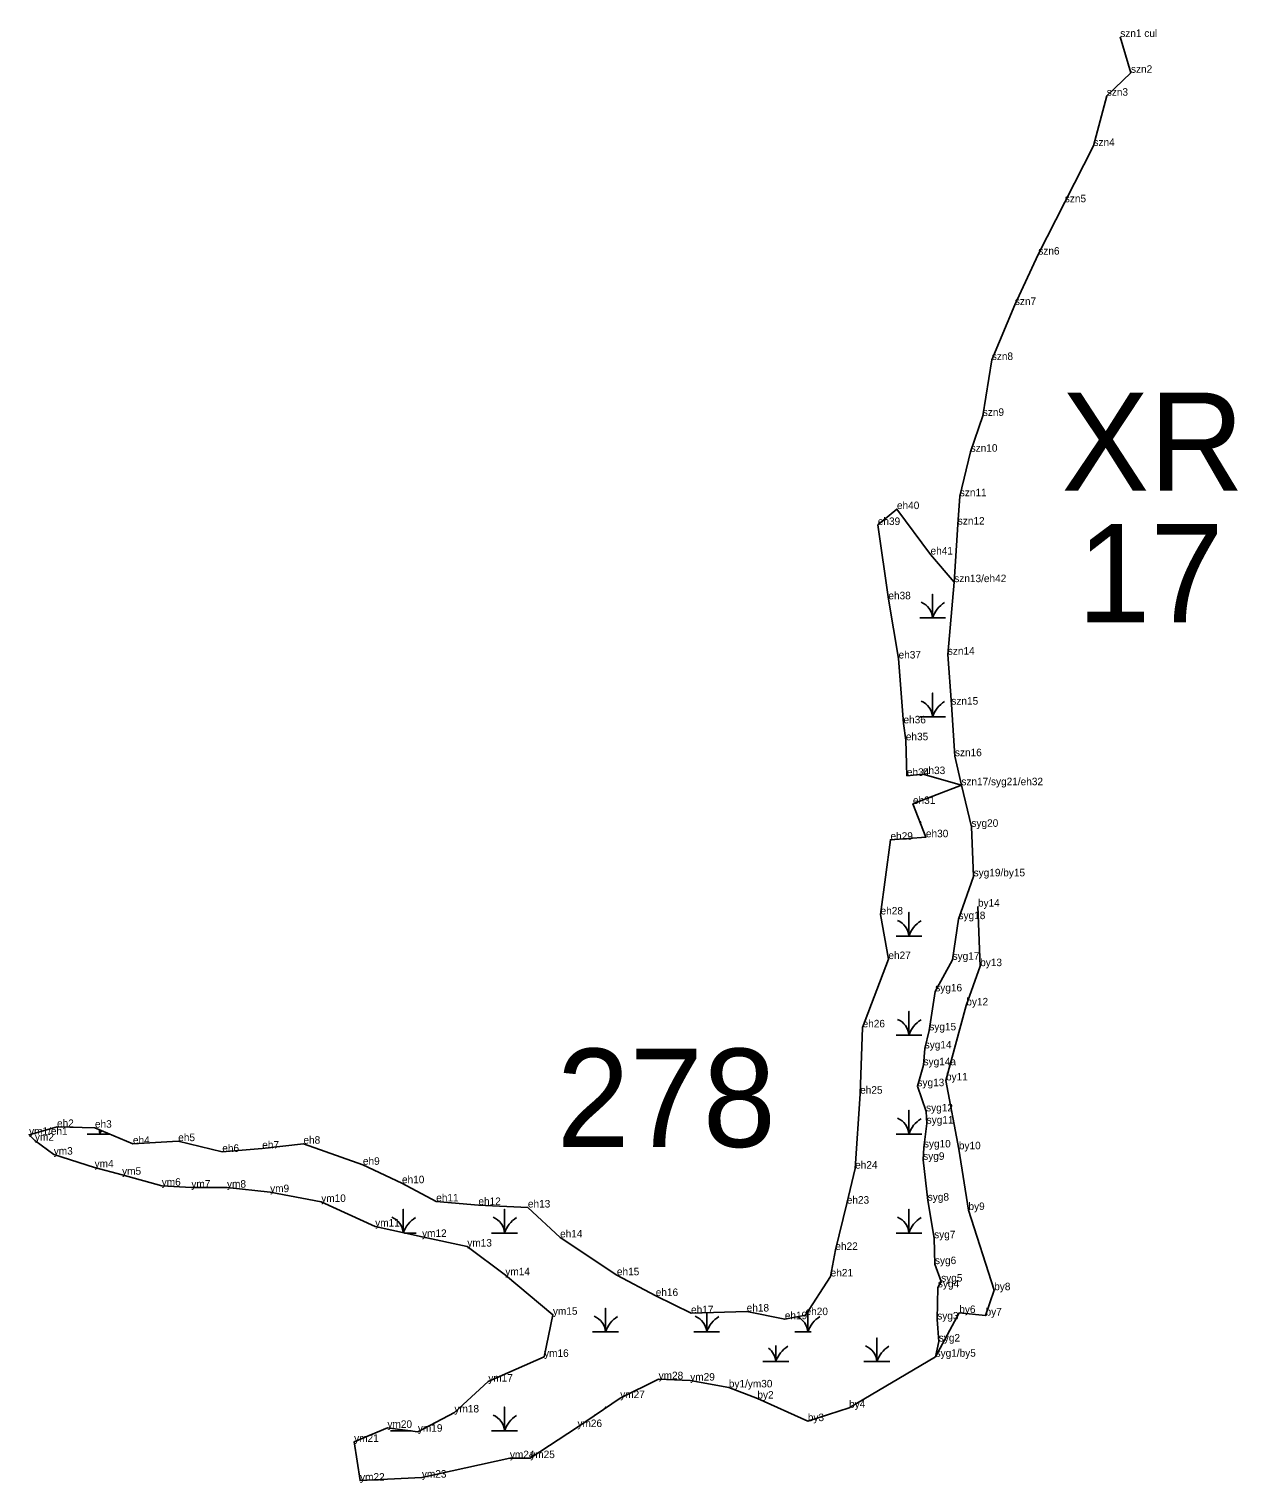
# Model space of a CAD drawing. Extents: x 2072529 to 2268796, y 436423 to 470406.
# Drawn here: x 2238515 to 2239319, y 438660 to 439627 of the extents above; entities that cross this region are included whole.
import ezdxf

# ---------------------------------------------------------------- set-up
doc = ezdxf.new("R2010")
doc.units = 0
for name, color, linetype in [('Default', 7, 'Continuous'), ('Exist Environmental Wetland Boundary', 7, 'Continuous'), ('Exist Environmental Wetland Boundary Cogo Comment', 7, 'Continuous'), ('Exist Hydro Jurisdictional Stream or Body of Water NEU Mitigable', 7, 'Continuous'), ('Exist Hydro Jurisdictional Stream or Body of Water NEU Mitigable Cogo Comment', 7, 'Continuous'), ('Exist Hydro Swamp or Marsh', 7, 'Continuous'), ('Old_Level_20', 7, 'Continuous')]:
    doc.layers.add(name, color=color, linetype=linetype)

msp = doc.modelspace()

# ---------------------------------------------------------------- linework, layer by layer
at = {"layer": 'Exist Environmental Wetland Boundary'}
for points in [[(2238980.17, 438723.98), (2238954.5, 438728.5), (2238933.48, 438729.42), (2238907.94, 438716.85), (2238879.5, 438697.62), (2238848.11, 438676.97), (2238834.56, 438676.88), (2238776.04, 438663.97), (2238734.94, 438661.98), (2238730.98, 438687.75), (2238753.14, 438697.08), (2238773.37, 438694.51), (2238797.69, 438707.34), (2238820.21, 438727.82), (2238857.31, 438744.3), (2238863.18, 438772.3), (2238831.54, 438798.55), (2238806.25, 438817.65), (2238776.16, 438824.05), (2238744.98, 438830.99), (2238709.11, 438847.32), (2238675.12, 438853.84), (2238646.44, 438856.82), (2238622.74, 438856.85), (2238603.03, 438858.12), (2238576.68, 438865.43), (2238558.41, 438870.32), (2238531.22, 438878.77), (2238518.73, 438888.08), (2238514.82, 438892), (2238533.4, 438897.17), (2238558.63, 438896.68), (2238583.89, 438885.99), (2238614, 438887.75), (2238643.32, 438880.62), (2238669.87, 438882.82), (2238697.27, 438886.05), (2238736.84, 438872.03), (2238762.81, 438859.76), (2238785.58, 438847.67), (2238813.64, 438845.28), (2238846.55, 438843.62), (2238867.95, 438823.73), (2238905.74, 438798.56), (2238931.56, 438784.78), (2238955.04, 438773.27), (2238992.04, 438774.46), (2239017.4, 438769.35), (2239031.2, 438772.05), (2239047.88, 438797.76), (2239051.03, 438815.39), (2239058.6, 438846.18), (2239064.17, 438869.46), (2239067.52, 438919.3), (2239069.12, 438963.43), (2239086.29, 439008.83), (2239081.09, 439038.49), (2239087.68, 439088.18), (2239111.25, 439089.84), (2239102.62, 439111.99), (2239134.83, 439124.43), (2239109.21, 439131.85), (2239098.58, 439130.7), (2239097.89, 439154.34), (2239096.33, 439165.59), (2239093.07, 439208.73), (2239086.28, 439248.1), (2239079.24, 439297.52), (2239091.98, 439308.07), (2239114.33, 439277.88), (2239130.1, 439259.51)], [(2238980.17, 438723.98), (2238999.17, 438716.6), (2239032.71, 438701.56), (2239060.14, 438710.42), (2239117.66, 438744.38), (2239133.42, 438773.47), (2239150.91, 438771.79), (2239156.64, 438788.62), (2239139.54, 438841.96), (2239133.15, 438882.35), (2239124.57, 438928.14), (2239138.11, 438978.03), (2239147.33, 439004.13), (2239145.84, 439043.72)]]:
    msp.add_lwpolyline(points, dxfattribs=at)
at = {"layer": 'Exist Hydro Jurisdictional Stream or Body of Water NEU Mitigable'}
msp.add_lwpolyline([(2239240.49, 439622.04), (2239247.61, 439598.24), (2239231.5, 439582.99), (2239222.67, 439549.6), (2239203.62, 439512.14), (2239185.96, 439477.33), (2239170.4, 439443.86), (2239155.04, 439407.24), (2239149.05, 439370.08), (2239140.98, 439346.22), (2239133.77, 439316.64), (2239132.43, 439297.8), (2239130.1, 439259.51), (2239125.8, 439211.29), (2239128.17, 439178.04), (2239130.54, 439143.75), (2239134.83, 439124.43), (2239141.51, 439096.78), (2239142.97, 439063.86), (2239132.92, 439035.39), (2239128.96, 439008.36), (2239117.45, 438987.35), (2239113.49, 438961.42), (2239110.45, 438949.43), (2239109.66, 438938.21), (2239105.6, 438924.29), (2239111.36, 438907.55), (2239111.76, 438899.44), (2239109.91, 438883.57), (2239109.43, 438875.34), (2239112.46, 438848.19), (2239116.71, 438823.21), (2239117.25, 438805.98), (2239121.39, 438794.34), (2239119.2, 438790.51), (2239118.77, 438769.16), (2239119.82, 438754.51), (2239117.66, 438744.38)], dxfattribs=at)
at = {"layer": 'Exist Hydro Swamp or Marsh'}
for points in [[(2239107.08, 439235.7), (2239115.68, 439235.7), (2239115.68, 439251.48), (2239115.68, 439235.7), (2239124.28, 439235.7)], [(2239107.08, 439169.9), (2239115.68, 439169.9), (2239115.68, 439185.68), (2239115.68, 439169.9), (2239124.28, 439169.9)], [(2239091.35, 439024.07), (2239099.95, 439024.07), (2239099.95, 439039.85), (2239099.95, 439024.07), (2239108.56, 439024.07)], [(2239091.35, 438958.27), (2239099.95, 438958.27), (2239099.95, 438974.05), (2239099.95, 438958.27), (2239108.56, 438958.27)], [(2239091.35, 438892.47), (2239099.95, 438892.47), (2239099.95, 438908.25), (2239099.95, 438892.47), (2239108.56, 438892.47)], [(2238553.35, 438892.47), (2238561.95, 438892.47), (2238561.95, 438895.27)], [(2238561.95, 438895.27), (2238561.95, 438892.47), (2238568.56, 438892.47)], [(2238763.7, 438826.83), (2238763.7, 438842.45), (2238763.7, 438826.83)], [(2238822.35, 438826.67), (2238830.95, 438826.67), (2238830.95, 438842.45), (2238830.95, 438826.67), (2238839.56, 438826.67)], [(2239091.35, 438826.67), (2239099.95, 438826.67), (2239099.95, 438842.45), (2239099.95, 438826.67), (2239108.56, 438826.67)], [(2238764.39, 438826.67), (2238772.31, 438826.67)], [(2238889.6, 438760.87), (2238898.2, 438760.87), (2238898.2, 438776.65), (2238898.2, 438760.87), (2238906.81, 438760.87)], [(2238956.85, 438760.87), (2238965.45, 438760.87), (2238965.45, 438773.6)], [(2238965.45, 438773.6), (2238965.45, 438760.87), (2238974.06, 438760.87)], [(2239024.1, 438760.87), (2239032.7, 438760.87), (2239032.7, 438774.37)], [(2239032.7, 438774.37), (2239032.7, 438760.87), (2239034.97, 438760.87)], [(2239002.78, 438741.14), (2239011.38, 438741.14), (2239011.38, 438751.82)], [(2239011.38, 438751.82), (2239011.38, 438741.14), (2239019.98, 438741.14)], [(2239070.03, 438741.14), (2239078.63, 438741.14), (2239078.63, 438756.92), (2239078.63, 438741.14), (2239087.23, 438741.14)], [(2238822.35, 438695.07), (2238830.95, 438695.07), (2238830.95, 438710.85), (2238830.95, 438695.07), (2238839.56, 438695.07)], [(2238898.2, 438710.26), (2238898.2, 438710.85), (2238898.2, 438710.26)], [(2238755.1, 438695.07), (2238763.7, 438695.07), (2238763.7, 438695.73)], [(2238763.7, 438695.73), (2238763.7, 438695.07), (2238768.92, 438695.07)]]:
    msp.add_lwpolyline(points, dxfattribs=at)
for centre, radius, start, end in [((2239103.42, 439234.81), 12.3, 4.14034, 67.53497), ((2239133.92, 439229.64), 19.22, 122.12745, 161.62219), ((2239103.42, 439169.01), 12.3, 4.14034, 67.53497), ((2239133.92, 439163.84), 19.22, 122.12745, 161.62219), ((2239118.2, 439083.81), 19.22, 122.12745, 124.16631), ((2239087.69, 439023.18), 12.3, 4.14034, 67.53497), ((2239118.2, 439018.01), 19.22, 122.12745, 161.62219), ((2239087.69, 438957.38), 12.3, 4.14034, 67.53497), ((2239118.2, 438952.21), 19.22, 122.12745, 161.62219), ((2239087.69, 438891.58), 12.3, 4.14034, 67.53497), ((2239118.2, 438886.41), 19.22, 122.12745, 161.62219), ((2238549.69, 438891.58), 12.3, 4.14034, 18.72156), ((2238580.2, 438886.41), 19.22, 153.93646, 161.62219), ((2238751.44, 438825.78), 12.3, 4.87114, 67.53497), ((2238781.95, 438820.61), 19.22, 122.12745, 161.17266), ((2238818.69, 438825.78), 12.3, 4.14034, 67.53497), ((2238849.2, 438820.61), 19.22, 122.12745, 161.62219), ((2239087.69, 438825.78), 12.3, 4.14034, 67.53497), ((2239118.2, 438820.61), 19.22, 122.12745, 161.62219), ((2238885.94, 438759.98), 12.3, 4.14034, 67.53497), ((2238916.45, 438754.81), 19.22, 122.12745, 161.62219), ((2238953.19, 438759.98), 12.3, 4.14034, 67.53497), ((2238983.7, 438754.81), 19.22, 122.12745, 161.62219), ((2239020.44, 438759.98), 12.3, 4.14034, 63.70318), ((2239050.95, 438754.81), 19.22, 122.12745, 161.62219), ((2239029.62, 438735.08), 19.22, 122.12745, 161.62219), ((2239066.36, 438740.25), 12.3, 4.14034, 67.53497), ((2239096.87, 438735.08), 19.22, 122.12745, 161.62219), ((2238999.11, 438740.25), 12.3, 4.14034, 52.40661), ((2238818.69, 438694.18), 12.3, 4.14034, 67.53497), ((2238849.2, 438689.01), 19.22, 122.12745, 161.62219), ((2238885.94, 438694.18), 12.3, 67.2043, 67.53497), ((2238751.44, 438694.18), 12.3, 4.14034, 7.28645), ((2238781.95, 438689.01), 19.22, 159.61604, 161.62219)]:
    msp.add_arc(centre, radius, start, end, dxfattribs=at)
at = {"layer": 'Old_Level_20'}
for p, q in [((2239240.49, 439622.04), (2239240.49, 439622.04)), ((2239247.61, 439598.24), (2239247.61, 439598.24)), ((2239231.5, 439582.99), (2239231.5, 439582.99)), ((2239222.67, 439549.6), (2239222.67, 439549.6)), ((2239203.62, 439512.14), (2239203.62, 439512.14)), ((2239185.96, 439477.33), (2239185.96, 439477.33)), ((2239170.4, 439443.86), (2239170.4, 439443.86)), ((2239155.04, 439407.24), (2239155.04, 439407.24)), ((2239149.05, 439370.08), (2239149.05, 439370.08)), ((2239140.98, 439346.22), (2239140.98, 439346.22)), ((2239133.77, 439316.64), (2239133.77, 439316.64)), ((2239091.98, 439308.07), (2239091.98, 439308.07)), ((2239079.24, 439297.52), (2239079.24, 439297.52)), ((2239132.43, 439297.8), (2239132.43, 439297.8)), ((2239114.33, 439277.88), (2239114.33, 439277.88)), ((2239130.1, 439259.51), (2239130.1, 439259.51)), ((2239086.28, 439248.1), (2239086.28, 439248.1)), ((2239093.07, 439208.73), (2239093.07, 439208.73)), ((2239125.8, 439211.29), (2239125.8, 439211.29)), ((2239128.17, 439178.04), (2239128.17, 439178.04)), ((2239096.33, 439165.59), (2239096.33, 439165.59)), ((2239097.89, 439154.34), (2239097.89, 439154.34)), ((2239130.54, 439143.75), (2239130.54, 439143.75)), ((2239098.58, 439130.7), (2239098.58, 439130.7)), ((2239109.21, 439131.85), (2239109.21, 439131.85)), ((2239134.83, 439124.43), (2239134.83, 439124.43)), ((2239134.83, 439124.43), (2239134.83, 439124.43)), ((2239102.62, 439111.99), (2239102.62, 439111.99)), ((2239111.25, 439089.84), (2239111.25, 439089.84)), ((2239141.51, 439096.78), (2239141.51, 439096.78)), ((2239087.68, 439088.18), (2239087.68, 439088.18)), ((2239142.97, 439063.86), (2239142.97, 439063.86)), ((2239145.84, 439043.72), (2239145.84, 439043.72)), ((2239081.09, 439038.49), (2239081.09, 439038.49)), ((2239132.92, 439035.39), (2239132.92, 439035.39)), ((2239086.29, 439008.83), (2239086.29, 439008.83)), ((2239128.96, 439008.36), (2239128.96, 439008.36)), ((2239147.33, 439004.13), (2239147.33, 439004.13)), ((2239117.45, 438987.35), (2239117.45, 438987.35)), ((2239138.11, 438978.03), (2239138.11, 438978.03)), ((2239069.12, 438963.43), (2239069.12, 438963.43)), ((2239113.49, 438961.42), (2239113.49, 438961.42)), ((2239110.45, 438949.43), (2239110.45, 438949.43)), ((2239109.66, 438938.21), (2239109.66, 438938.21)), ((2239124.57, 438928.14), (2239124.57, 438928.14)), ((2239067.52, 438919.3), (2239067.52, 438919.3)), ((2239105.6, 438924.29), (2239105.6, 438924.29)), ((2239111.36, 438907.55), (2239111.36, 438907.55)), ((2238533.4, 438897.17), (2238533.4, 438897.17)), ((2238558.63, 438896.68), (2238558.63, 438896.68)), ((2239111.76, 438899.44), (2239111.76, 438899.44)), ((2238514.82, 438892), (2238514.82, 438892)), ((2238518.73, 438888.08), (2238518.73, 438888.08)), ((2238614, 438887.75), (2238614, 438887.75)), ((2238531.22, 438878.77), (2238531.22, 438878.77)), ((2238583.89, 438885.99), (2238583.89, 438885.99)), ((2238643.32, 438880.62), (2238643.32, 438880.62)), ((2238669.87, 438882.82), (2238669.87, 438882.82)), ((2238697.27, 438886.05), (2238697.27, 438886.05)), ((2239109.91, 438883.57), (2239109.91, 438883.57)), ((2239133.15, 438882.35), (2239133.15, 438882.35)), ((2238558.41, 438870.32), (2238558.41, 438870.32)), ((2238736.84, 438872.03), (2238736.84, 438872.03)), ((2239064.17, 438869.46), (2239064.17, 438869.46)), ((2239109.43, 438875.34), (2239109.43, 438875.34)), ((2238576.68, 438865.43), (2238576.68, 438865.43)), ((2238603.03, 438858.12), (2238603.03, 438858.12)), ((2238762.81, 438859.76), (2238762.81, 438859.76)), ((2238622.74, 438856.85), (2238622.74, 438856.85)), ((2238646.44, 438856.82), (2238646.44, 438856.82)), ((2238675.12, 438853.84), (2238675.12, 438853.84)), ((2238785.58, 438847.67), (2238785.58, 438847.67)), ((2239112.46, 438848.19), (2239112.46, 438848.19)), ((2238709.11, 438847.32), (2238709.11, 438847.32)), ((2238813.64, 438845.28), (2238813.64, 438845.28)), ((2238846.55, 438843.62), (2238846.55, 438843.62)), ((2239058.6, 438846.18), (2239058.6, 438846.18)), ((2239139.54, 438841.96), (2239139.54, 438841.96)), ((2238744.98, 438830.99), (2238744.98, 438830.99)), ((2238776.16, 438824.05), (2238776.16, 438824.05)), ((2238867.95, 438823.73), (2238867.95, 438823.73)), ((2239116.71, 438823.21), (2239116.71, 438823.21)), ((2238806.25, 438817.65), (2238806.25, 438817.65)), ((2239051.03, 438815.39), (2239051.03, 438815.39)), ((2239117.25, 438805.98), (2239117.25, 438805.98)), ((2238831.54, 438798.55), (2238831.54, 438798.55)), ((2238905.74, 438798.56), (2238905.74, 438798.56)), ((2239047.88, 438797.76), (2239047.88, 438797.76)), ((2239119.2, 438790.51), (2239119.2, 438790.51)), ((2239121.39, 438794.34), (2239121.39, 438794.34)), ((2238931.56, 438784.78), (2238931.56, 438784.78)), ((2239156.64, 438788.62), (2239156.64, 438788.62)), ((2238863.18, 438772.3), (2238863.18, 438772.3)), ((2238955.04, 438773.27), (2238955.04, 438773.27)), ((2238992.04, 438774.46), (2238992.04, 438774.46)), ((2239031.2, 438772.05), (2239031.2, 438772.05)), ((2239133.42, 438773.47), (2239133.42, 438773.47)), ((2239150.91, 438771.79), (2239150.91, 438771.79)), ((2239017.4, 438769.35), (2239017.4, 438769.35)), ((2239118.77, 438769.16), (2239118.77, 438769.16)), ((2239119.82, 438754.51), (2239119.82, 438754.51)), ((2238857.31, 438744.3), (2238857.31, 438744.3)), ((2239117.66, 438744.38), (2239117.66, 438744.38)), ((2239117.66, 438744.38), (2239117.66, 438744.38)), ((2238820.21, 438727.82), (2238820.21, 438727.82)), ((2238933.48, 438729.42), (2238933.48, 438729.42)), ((2238954.5, 438728.5), (2238954.5, 438728.5)), ((2238980.17, 438723.98), (2238980.17, 438723.98)), ((2238907.94, 438716.85), (2238907.94, 438716.85)), ((2238999.17, 438716.6), (2238999.17, 438716.6)), ((2238797.69, 438707.34), (2238797.69, 438707.34)), ((2239060.14, 438710.42), (2239060.14, 438710.42)), ((2238753.14, 438697.08), (2238753.14, 438697.08)), ((2238773.37, 438694.51), (2238773.37, 438694.51)), ((2238879.5, 438697.62), (2238879.5, 438697.62)), ((2239032.71, 438701.56), (2239032.71, 438701.56)), ((2238730.98, 438687.75), (2238730.98, 438687.75)), ((2238834.56, 438676.88), (2238834.56, 438676.88)), ((2238848.11, 438676.97), (2238848.11, 438676.97)), ((2238776.04, 438663.97), (2238776.04, 438663.97)), ((2238734.94, 438661.98), (2238734.94, 438661.98))]:
    msp.add_line(p, q, dxfattribs=at)

# ---------------------------------------------------------------- texts
at = {"layer": 'Default'}
for s, p in [('XR', (2239201.4, 439320.26)), ('17', (2239211.94, 439232.86)), ('278', (2238865.66, 438883.91))]:
    msp.add_text(s, height=65.34, dxfattribs=at).set_placement(p)
at = {"layer": 'Exist Environmental Wetland Boundary Cogo Comment'}
for s, p in [('eh40', (2239091.98, 439308.07)), ('eh39', (2239079.24, 439297.52)), ('eh41', (2239114.33, 439277.88)), ('eh38', (2239086.28, 439248.1)), ('eh37', (2239093.07, 439208.73)), ('eh36', (2239096.33, 439165.59)), ('eh35', (2239097.89, 439154.34)), ('eh34', (2239098.58, 439130.7)), ('eh33', (2239109.21, 439131.85)), ('eh31', (2239102.62, 439111.99)), ('eh29', (2239087.68, 439088.18)), ('eh30', (2239111.25, 439089.84)), ('eh28', (2239081.09, 439038.49)), ('by14', (2239145.84, 439043.72)), ('eh27', (2239086.29, 439008.83)), ('by13', (2239147.33, 439004.13)), ('by12', (2239138.11, 438978.03)), ('eh26', (2239069.12, 438963.43)), ('by11', (2239124.57, 438928.14)), ('eh25', (2239067.52, 438919.3)), ('ym1/eh1', (2238514.82, 438892)), ('eh2', (2238533.4, 438897.17)), ('eh3', (2238558.63, 438896.68)), ('ym2', (2238518.73, 438888.08)), ('eh4', (2238583.89, 438885.99)), ('eh5', (2238614, 438887.75)), ('eh7', (2238669.87, 438882.82)), ('eh8', (2238697.27, 438886.05)), ('by10', (2239133.15, 438882.35)), ('ym3', (2238531.22, 438878.77)), ('eh6', (2238643.32, 438880.62)), ('eh9', (2238736.84, 438872.03)), ('ym4', (2238558.41, 438870.32)), ('ym5', (2238576.68, 438865.43)), ('eh24', (2239064.17, 438869.46)), ('ym6', (2238603.03, 438858.12)), ('ym7', (2238622.74, 438856.85)), ('ym8', (2238646.44, 438856.82)), ('ym9', (2238675.12, 438853.84)), ('eh10', (2238762.81, 438859.76)), ('ym10', (2238709.11, 438847.32)), ('eh11', (2238785.58, 438847.67)), ('eh12', (2238813.64, 438845.28)), ('eh13', (2238846.55, 438843.62)), ('eh23', (2239058.6, 438846.18)), ('by9', (2239139.54, 438841.96)), ('ym11', (2238744.98, 438830.99)), ('ym12', (2238776.16, 438824.05)), ('eh14', (2238867.95, 438823.73)), ('ym13', (2238806.25, 438817.65)), ('eh22', (2239051.03, 438815.39)), ('ym14', (2238831.54, 438798.55)), ('eh15', (2238905.74, 438798.56)), ('eh21', (2239047.88, 438797.76)), ('eh16', (2238931.56, 438784.78)), ('by8', (2239156.64, 438788.62)), ('ym15', (2238863.18, 438772.3)), ('eh17', (2238955.04, 438773.27)), ('eh18', (2238992.04, 438774.46)), ('eh19', (2239017.4, 438769.35)), ('eh20', (2239031.2, 438772.05)), ('by6', (2239133.42, 438773.47)), ('by7', (2239150.91, 438771.79)), ('ym16', (2238857.31, 438744.3)), ('ym17', (2238820.21, 438727.82)), ('ym28', (2238933.48, 438729.42)), ('ym29', (2238954.5, 438728.5)), ('ym27', (2238907.94, 438716.85)), ('by1/ym30', (2238980.17, 438723.98)), ('by2', (2238999.17, 438716.6)), ('ym18', (2238797.69, 438707.34)), ('by4', (2239060.14, 438710.42)), ('ym26', (2238879.5, 438697.62)), ('by3', (2239032.71, 438701.56)), ('ym21', (2238730.98, 438687.75)), ('ym20', (2238753.14, 438697.08)), ('ym19', (2238773.37, 438694.51)), ('ym24', (2238834.56, 438676.88)), ('ym25', (2238848.11, 438676.97)), ('ym22', (2238734.94, 438661.98)), ('ym23', (2238776.04, 438663.97))]:
    msp.add_text(s, height=5, dxfattribs=at).set_placement(p)
at = {"layer": 'Exist Hydro Jurisdictional Stream or Body of Water NEU Mitigable Cogo Comment'}
for s, p in [('szn1 cul', (2239240.49, 439622.04)), ('szn2', (2239247.61, 439598.24)), ('szn3', (2239231.5, 439582.99)), ('szn4', (2239222.67, 439549.6)), ('szn5', (2239203.62, 439512.14)), ('szn6', (2239185.96, 439477.33)), ('szn7', (2239170.4, 439443.86)), ('szn8', (2239155.04, 439407.24)), ('szn9', (2239149.05, 439370.08)), ('szn10', (2239140.98, 439346.22)), ('szn11', (2239133.77, 439316.64)), ('szn12', (2239132.43, 439297.8)), ('szn13/eh42', (2239130.1, 439259.51)), ('szn14', (2239125.8, 439211.29)), ('szn15', (2239128.17, 439178.04)), ('szn16', (2239130.54, 439143.75)), ('szn17/syg21/eh32', (2239134.83, 439124.43)), ('syg20', (2239141.51, 439096.78)), ('syg19/by15', (2239142.97, 439063.86)), ('syg18', (2239132.92, 439035.39)), ('syg17', (2239128.96, 439008.36)), ('syg16', (2239117.45, 438987.35)), ('syg15', (2239113.49, 438961.42)), ('syg14', (2239110.45, 438949.43)), ('syg14a', (2239109.66, 438938.21)), ('syg13', (2239105.6, 438924.29)), ('syg12', (2239111.36, 438907.55)), ('syg11', (2239111.76, 438899.44)), ('syg10', (2239109.91, 438883.57)), ('syg9', (2239109.43, 438875.34)), ('syg8', (2239112.46, 438848.19)), ('syg7', (2239116.71, 438823.21)), ('syg6', (2239117.25, 438805.98)), ('syg5', (2239121.39, 438794.34)), ('syg4', (2239119.2, 438790.51)), ('syg3', (2239118.77, 438769.16)), ('syg2', (2239119.82, 438754.51)), ('syg1/by5', (2239117.66, 438744.38))]:
    msp.add_text(s, height=5, dxfattribs=at).set_placement(p)

doc.saveas('drawing.dxf')
